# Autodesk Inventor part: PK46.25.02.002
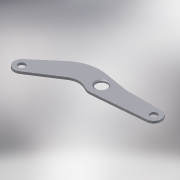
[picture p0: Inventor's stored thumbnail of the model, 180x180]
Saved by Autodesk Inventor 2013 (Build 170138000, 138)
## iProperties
Created: 2005-04
Part Number: PK46.25.02.002
Material: Steel, Mild
Document SubType Name: Modeling
Designer: salex
Manufacturer: Standard
Standards Organization: Custom
Density: 7.86 g/cm^3
Mass: 88732.9 g
Surface Area: 8949.05 cm^2
Volume: 11289.2 cm^3
Author: salex
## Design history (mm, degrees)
sketch "Эскиз1"
  geometry: L1 (0, 0)-(690, 0); L2 (690, 100)-(225, 100); L3 (225, 100)-(-92.453, 153.139); L4 (698.696, -99.621)-(13.913, -159.394); L5 (-71.528, -143.121)-(-105.59, -126.098); L6 (-695.946, -389.132)-(-303.108, -136.736); L7 (-814.936, -228.952)-(-499.681, 40.24); C1 r 75 at (0, 0); C2 r 45 at (690, 0); C3 r 45 at (-750, -305); A1 r 100 centre (690, 0) between (698.696, -99.621) and (690, 100); A2 r 100 centre (-750, -305) between (-814.936, -228.952) and (-695.946, -389.132); A3 r 200 centre (-195, -305) between (-105.59, -126.098) and (-303.108, -136.736); A4 r 160 centre (0, 0) between (-71.528, -143.121) and (13.913, -159.394); A5 r 500 centre (-175, -340) between (-92.453, 153.139) and (-499.681, 40.24)
  constraints: 14 end point, 10 point on circle, 10 tangent, 8 centre point, 3 coincident, 2 equal radius, 1 horizontal, 1 parallel, 1 other
  dimensions: "d0" = 690 distance of A1.centre A4.centre; "d1" = 90 diameter of C3; "d2" = 200 diameter of A2; "d4" = 400 diameter of A3; "d5" = 1440 horizontal distance of C3.centre L1.end; "d6" = 305 distance from line of L1 A3.centre; "d7" = 195 horizontal distance of L1.start A3.centre; "d8" = 160 radius of A4; "d9" = 150 diameter of C1; "d10" = 340 distance from line of A5.centre L1; "d11" = 175 horizontal distance of L1.start A5.centre; "d12" = 500 radius of A5; "d13" = 225 horizontal distance of L2.end L1.start; "d14" = 305 distance from line of C3.centre L1
extrude "Выдавливание1" new body sketch "Эскиз1" distance "d15" = 30; taper "d16" = 0 deg
chamfer "Фаска1" distance "d17" = 12; stored, may be unused: second distance "d18" = 2, angle "d19" = 45 deg
body "Solid1"
